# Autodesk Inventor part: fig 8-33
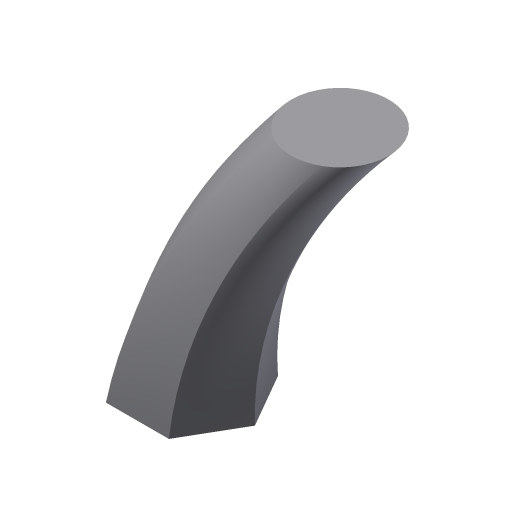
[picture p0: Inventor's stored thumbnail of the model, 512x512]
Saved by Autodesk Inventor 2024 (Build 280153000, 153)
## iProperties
Shininess: 77.0
Angle Display Precision: 2
Document Length Units: 11269
Document Angle Units: 11279
Document Time Units: 11290
Document Mass Units: 11283
Document Length Units Precision: 3
Document Angle Units Precision: 2
Created: 2001-12
Part Number: fig 8-33
Document SubType Name: Modeling
Designer: CADSoft
Density: 1 g/cm^3
Material: Generic
Appearance: Default
Density: 0.0
Volumn: 0.0
Area: 0.0
PropertySet Name: Model Information
Control State: 0
Master: False
Checked Out: False
Author: CADSoft
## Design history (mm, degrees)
workplane "Work Plane3"
workplane "Work Plane4"
sketch "Sketch12"
  geometry: L1 (0, 10.598)-(9.178, -5.299); L2 (9.178, -5.299)-(-9.178, -5.299); L3 (-9.178, -5.299)-(0, 10.598); 1 further point
  constraints: 6 end point, 5 other
workplane "Work Plane5"
workplane "Work Plane6"
workplane "Work Plane7"
sketch "Sketch16"
  geometry: A1 r 72.799 centre (23.007, 110.594) between (0, 41.527) and (70, 54.995); 1 further point
  constraints: 2 point on circle, 1 centre point
loft "Loft5" sketch "Sketch16" dims "d57" = 0, "d58" = 90 deg, "d59" = 0, "d60" = 90 deg, "d61" = 0, "d62" = 90 deg
body "Solid2"
sketch "Sketch1"
  geometry: L1 (19.387, 0)-(9.693, -16.79); L2 (9.693, -16.79)-(-9.693, -16.79); L3 (-9.693, -16.79)-(-19.387, 0); L4 (-19.387, 0)-(-9.693, 16.79); L5 (-9.693, 16.79)-(9.693, 16.79); L6 (9.693, 16.79)-(19.387, 0); 1 further point
  constraints: 12 end point, 11 other
sketch "Sketch2"
  geometry: C1 r 15 at (23.06, 22.535)
  constraints: 1 centre point
